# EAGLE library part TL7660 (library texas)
CMOS VOLTAGE CONVERTER Source: http://focus.ti.com/lit/ds/scas794/scas794.pdf
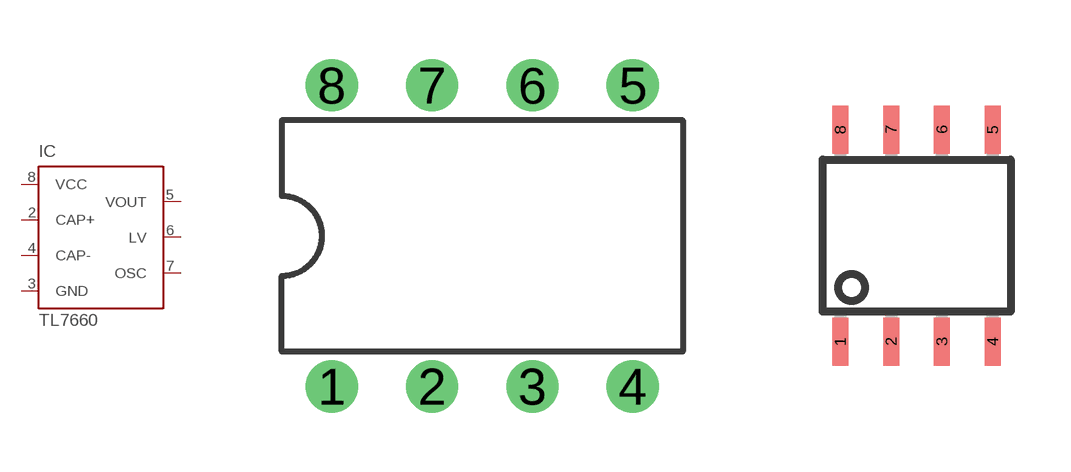
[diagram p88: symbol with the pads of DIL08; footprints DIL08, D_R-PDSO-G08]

Designator prefix IC

## TL7660P (MPN: TL7660CP; OC_FARNELL: 1755283; OC_NEWARK: 14M2447)  [DIL08]
2  CAP+  pas
3  GND  pwr
4  CAP-  pas
5  VOUT  pas
6  LV  pas
7  OSC  in
8  VCC  pwr

## TL7660D (MPN: TL7660CD; OC_FARNELL: 1755282; OC_NEWARK: 14M2439)  [D_R-PDSO-G08]
Pads as for DIL08

## TL7660DGK (OC_FARNELL: unknown; OC_NEWARK: unknown)  [DGK_S-PDSO-G8]
Pads as for DIL08

## Footprint DIL08 (pad centres in mm)
Dual In Line Package
drill 0.813 pad 1.27 round: 1 -3.81,-3.81; 2 -1.27,-3.81; 3 1.27,-3.81; 4 3.81,-3.81; 5 3.81,3.81; 6 1.27,3.81; 7 -1.27,3.81; 8 -3.81,3.81

## Footprint D_R-PDSO-G08 (pad centres in mm)
PLASTIC SMALL-OUTLINE PACKAGE SO 14 JEDEC MS-012, D Type Source: www.ti.com/.. slvs087l.pdf
smd 0.4 x 1.2: 1 -1.905,-2.65; 2 -0.635,-2.65; 3 0.635,-2.65; 4 1.905,-2.65; 5 1.905,2.65; 6 0.635,2.65; 7 -0.635,2.65; 8 -1.905,2.65

## Footprint DGK_S-PDSO-G8 (pad centres in mm)
DGK (S-PDSO-G8) Source: http://focus.ti.com/lit/ds/scas794/scas794.pdf
smd 0.4 x 1: 1 -0.975,-2.2; 2 -0.325,-2.2; 3 0.325,-2.2; 4 0.975,-2.2; 5 0.975,2.2; 6 0.325,2.2; 7 -0.325,2.2; 8 -0.975,2.2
